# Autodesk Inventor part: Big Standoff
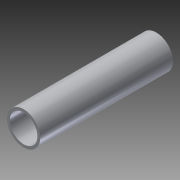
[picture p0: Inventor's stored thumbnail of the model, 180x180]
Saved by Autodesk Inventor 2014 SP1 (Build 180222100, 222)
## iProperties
Created: 2014-08
Part Number: Big Standoff
Material: Aluminum 6061
Document SubType Name: Modeling
Designer: User
Density: 2.71 g/cm^3
Appearance: Aluminum - Flat
Author: User
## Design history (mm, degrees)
sketch "Sketch1"
  geometry: C1 r 9.525 at (0, 0); C2 r 7.938 at (0, 0); 1 further point
  constraints: 2 centre point, 2 coincident
  dimensions: "d0" = 19.05 diameter of C1; "d1" = 15.875 diameter of C2
extrude "Extrusion1" new body sketch "Sketch1" distance "d2" = 76.2; taper "d3" = 0 deg
body "Solid1"
